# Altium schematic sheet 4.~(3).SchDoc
size 420 x 297 mm
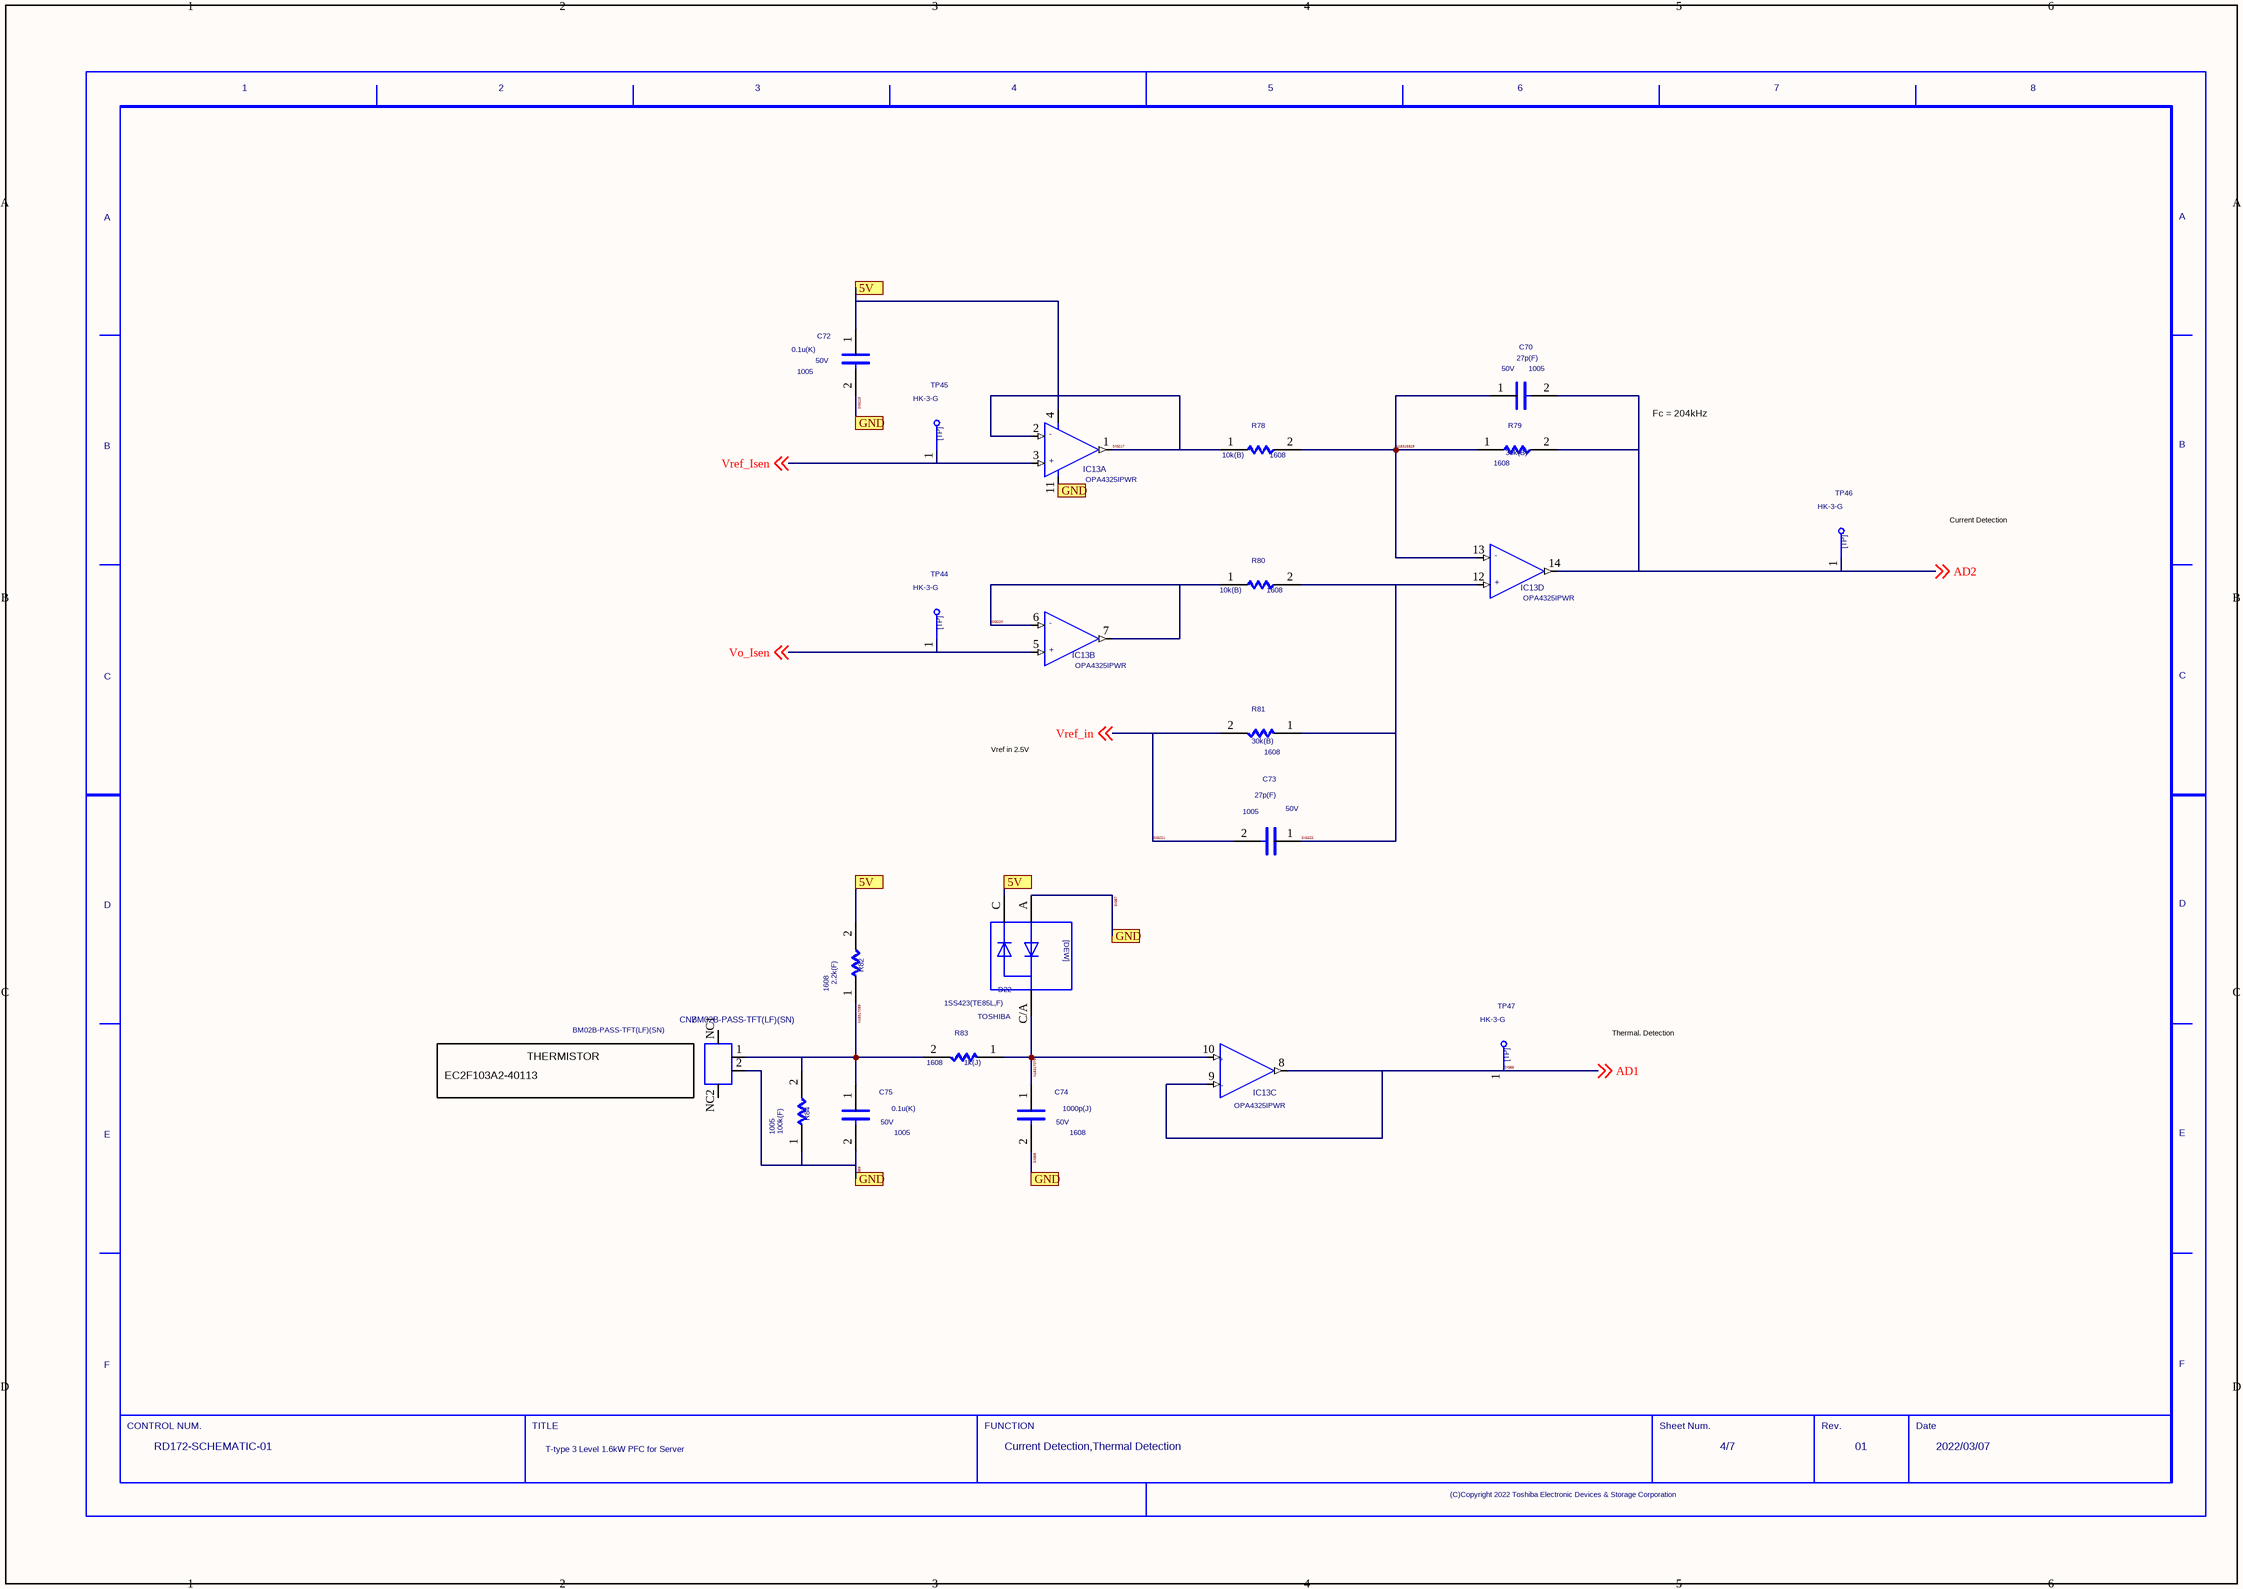
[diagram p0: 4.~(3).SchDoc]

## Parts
C70  SIZECODESMD: 1005  VAL2: 50V  VAL1: 27p(F)  (hidden comment: C)
C72  SIZECODESMD: 1005  VAL2: 50V  VAL1: 0.1u(K)  (hidden comment: C)
C73  SIZECODESMD: 1005  VAL2: 50V  VAL1: 27p(F)  (hidden comment: C)
C74  SIZECODESMD: 1608  VAL2: 50V  VAL1: 1000p(J)  (hidden comment: C)
C75  SIZECODESMD: 1005  VAL2: 50V  VAL1: 0.1u(K)  (hidden comment: C)
CN7  BM02B-PASS-TFT(LF)(SN)
D22  USERCOMPTEXT3: TOSHIBA  VAL3: 1SS423(TE85L,F)  (hidden comment: DEW)
IC13  VAL3: OPA4325IPWR  (hidden comment: OPA4325IPWR_4)  (parts A,B,C,D of 4)
R78  SIZECODESMD: 1608  VAL1: 10k(B)  (hidden comment: R)
R79  SIZECODESMD: 1608  VAL1: 30k(B)  (hidden comment: R)
R80  SIZECODESMD: 1608  VAL1: 10k(B)  (hidden comment: R)
R81  SIZECODESMD: 1608  VAL1: 30k(B)  (hidden comment: R)
R82  SIZECODESMD: 1608  VAL1: 2.2k(F)  (hidden comment: R)
R83  SIZECODESMD: 1608  VAL1: 1k(J)  (hidden comment: R)
R84  SIZECODESMD: 1005  VAL1: 100k(F)  (hidden comment: R)
TP44  VAL3: HK-3-G  (hidden comment: TP)
TP45  VAL3: HK-3-G  (hidden comment: TP)
TP46  VAL3: HK-3-G  (hidden comment: TP)
TP47  VAL3: HK-3-G  (hidden comment: TP)
U?  DATE: 2022/03/07  REVISION: 01  SHEETNUMBER: 4/7  FUNCTION: Current Detection,Thermal Detection  TITLE: T-type 3 Level 1.6kW PFC for Server  DRAWINGNUMBER: RD172-SCHEMATIC-01  (hidden comment: WAKU_DEF100)

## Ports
5V, GND

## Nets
5V: C72.1 D22.C IC13.4(V+) R82.2 ; port 5V
AD2: C70.2 IC13.14 R79.2 TP46.1 ; off-sheet AD2
N18316829: C70.1 IC13.13 R78.2 R79.1
N18317079: C74.1 D22.C/A(AC) IC13.10 R83.1
N18317089: C75.1 CN7.1 R82.1 R83.2 R84.2
SIG55: IC13.8 IC13.9 TP47.1 ; off-sheet AD1  [also labelled AD1]
SIG217: IC13.1(OUT) IC13.2(IN-) R78.1
SIG219: C72.2 C74.2 C75.2 CN7.2 D22.A IC13.11(V-) R84.1 ; port GND  [also labelled SIG57, SIG58, SIG59]
SIG220: IC13.6 IC13.7 R80.1
SIG221: C73.2 R81.2 ; off-sheet Vref_in  [also labelled Vref_in]
SIG222: C73.1 IC13.12 R80.2 R81.1
Vo_Isen: IC13.5 TP44.1 ; off-sheet Vo_Isen
Vref_Isen: IC13.3(IN+) TP45.1 ; off-sheet Vref_Isen

Not connected (* = marked no-connect by the designer): CN7 NC1(PAD1) NC2(PAD2)

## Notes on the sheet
- Fc = 204kHz
- Current Detection
- Vref in 2.5V
- THERMISTOR
- Thermal. Detection
- EC2F103A2-40113

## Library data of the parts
C70 C73 = C: OriginalSymbolOrigin: (2540,7620); COMP: -C-GCM1555C1H270FA16D
C72 C75 = C: OriginalSymbolOrigin: (2540,7620); COMP: -C-UMK105BJ104KV-F
C74 = C: OriginalSymbolOrigin: (2540,7620); COMP: -C-GRM1885C1H102JA01D
CN7 = BM02B_PASS_TFT_LF__SN_: Connector, 250V, 3A; MANUFACTURER: JST; COMP: -CN-BM02B-PASS-TFT_LF_SN; NOTE: 2pin; TIME: 16:53:54; UPDATEUSER: t5459927; SAVECOUNT: 1; SAVEAREA0: -5711,-10440,12927,3224; OriginalSymbolOrigin: (0,0); REFERENCE TEMPLATE: CN; INSTANCENAME: INS18317090
D22 = DEW: SAVEAREA0: -10024,-234,32508,20938; TIME: 14:49:55; UPDATEUSER: 19990028; UPDATETIME: 14:00:58; SAVECOUNT: 4; OriginalSymbolOrigin: (5080,17780); COMP: -D-1SS423_TE85L_F_AC
IC13 = OPA4325IPWR_4: COMP: -IC-OPA4325IPWR; TIME: 16:31:59; UPDATEUSER: t5459927; UPDATETIME: 16:35:50; SAVECOUNT: 11; SAVEAREA0: -17633,-13280,32685,23610; OriginalSymbolOrigin: (2540,10160); CaptureCellPackProp: OPA4325IPWR_4A; FUNCN: OPA4325IPWR_1
R78 R80 = R: OriginalSymbolOrigin: (5080,5080); VAL2: 100mW; COMP: -R-ERA3AEB103V
R79 R81 = R: OriginalSymbolOrigin: (5080,5080); VAL2: 100mW; COMP: -R-ERA3AEB203V
R82 = R: OriginalSymbolOrigin: (5080,5080); COMP: -R-ERJ3EKF2201V; VAL2: 100mW
R83 = R: OriginalSymbolOrigin: (5080,5080); COMP: -R-RK73B1JTTD102J; VAL2: 125mW
R84 = R: OriginalSymbolOrigin: (5080,5080); COMP: -R-RK73H1ETTP1003F; VAL2: 100mW
TP44-TP47 = TP: TIME: 16:12:21; UPDATEUSER: fukuda-y; UPDATETIME: 16:18:11; SAVECOUNT: 2; SAVEAREA0: -242,-92,12810,7836; OriginalSymbolOrigin: (0,7620); COMP: -TP-HK-3-G
U? = WAKU_DEF100: PLOTTIME: HH:MM; SAVEAREA0: 148187,-66180,486823,89919; TIME: 14:30:25; UPDATEUSER: t5459927; UPDATETIME: 09:34:24; SAVECOUNT: 6; OriginalSymbolOrigin: (10160,284480)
